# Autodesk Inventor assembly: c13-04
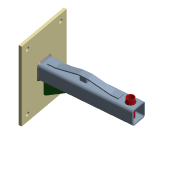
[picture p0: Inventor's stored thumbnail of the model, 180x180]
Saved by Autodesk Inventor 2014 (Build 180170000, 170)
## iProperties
Created: 2011-01
Part Number: c13-04
Document SubType Name: Weldment
Designer: Thom Tremblay
Weld Material: Welded Steel Mild
_SolveAssemblyDoc: Frame Generator Solve Assembly
_Version: 15.0.0
Author: Thom Tremblay
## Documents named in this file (5)
- C:\Inventor 2014 Essentials\Assemblies\Chapter 13\c13-04.iam
- C:\Inventor 2014 Essentials\Parts\Chapter 13\c13-01.ipt
- C:\Inventor 2014 Essentials\Parts\Chapter 13\c13-02.ipt
- C:\Inventor 2014 Essentials\Assemblies\Chapter 13\Frame\Frame c13-01.iam
- C:\Inventor 2014 Essentials\Parts\Chapter 13\c13-03.ipt
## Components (4 placed, 4 different names)
1. c13-01:1 — Mate:2
2. c13-02:1 — Flush:1
3. Frame c13-01:1 [sub-assembly] — Mate:3
4. c13-03:1 — Mate:1, Mate:2, Mate:3
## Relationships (4: Mate 3, Flush 1)
- Flush:1: c13-02:1
- Mate:1: c13-03:1
- Mate:2: c13-01:1 ↔ c13-03:1
- Mate:3: Frame c13-01:1 ↔ c13-03:1
